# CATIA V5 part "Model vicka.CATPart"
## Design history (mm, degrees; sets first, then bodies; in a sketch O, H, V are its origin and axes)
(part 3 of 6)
    reference projected circle E1 centre (31.0473, 28.8138) radius 2.465 from edge [end face of Pad29 | face of Pad29 from Sketch61.E2]
    construction line L5 (31.0473, 24.4443) -> (31.0473, 35.3752)
    reference projected point E2 (31.0473, 28.8138) from Point1
    point P7 (36.7139, 21.5019)
    point P8 (36.1649, 23.5509)
    line L6 (36.1649, 23.5509) -> (36.7139, 21.5019)
    point P9 (36.1649, 23.5509)
    point P10 (38.1649, 27.015)
    line L7 (38.1649, 27.015) -> (36.1649, 23.5509)
    point P12 (36.7139, 21.5019)
    line L8 (36.7139, 21.5019) -> (40.2139, 27.564)
    point P13 (38.1649, 27.015)
    line L9 (40.2139, 27.564) -> (38.1649, 27.015)
    point P15 (23.9298, 27.015)
    point P16 (25.9298, 23.5509)
    line L10 (25.9298, 23.5509) -> (23.9298, 27.015)
    point P17 (25.9298, 23.5509)
    point P18 (25.3807, 21.5019)
    line L11 (25.3807, 21.5019) -> (25.9298, 23.5509)
    point P19 (21.8807, 27.564)
    point P20 (23.9298, 27.015)
    line L12 (23.9298, 27.015) -> (21.8807, 27.564)
    point P21 (25.3807, 21.5019)
    point P22 (21.8807, 27.564)
    line L13 (21.8807, 27.564) -> (25.3807, 21.5019)
    length L1 = 4
    distance L3 L1 = 1.5
    angle L2 L1 = 135
    distance L1 E1 = 4.6
    distance P3 L5 = 3.5
    distance L5 E2 = 0
    length L3 = 7
    distance P7 L5 = 5.6666
    angle L6 L1 = 255
    length L7 = 4
    distance L7 E1 = 9.5284
    angle L3 L7 = 60 (reference)
    angle L2 L7 = 15
    length L8 = 7
    distance P12 L5 = 5.6666
    angle L8 L1 = 300 (reference)
    angle L8 L7 = 180 (reference)
    length L9 = 2.1213
    length L6 = 2.1213
    distance L7 L8 = 1.5
    angle L9 L8 = 45
    length L10 = 4
    distance L10 E1 = 9.5284
    angle L3 L10 = 300 (reference)
    angle L8 L10 = 60 (reference)
    angle L6 L10 = 15
    distance P19 L5 = 9.1666
    angle L12 L1 = 15
    length L13 = 7
    distance P22 L5 = 9.1666
    angle L13 L1 = 60 (reference)
    angle L13 L10 = 180 (reference)
    angle L13 L7 = 300 (reference)
    distance L13 L10 = 1.5
    length L12 = 2.1213
    length L11 = 2.1213
    distance P18 P21 = 0
    distance P8 P9 = 0
    distance P13 P10 = 0
    horizontal: L1 H, L3 H
    vertical: L5 V
    coincidence: P20 P15, P16 P17
  Pocket16: profile Sketch62, direction (-0.9237, 0.2709, 0.2709), length 2.2
  Sketch63 on end face of Pad29, origin (-16.699, 4.8982, 4.8982), H (0.2815, 0.9596, 0), V (0.26, -0.0763, 0.9626)
    circle A1 centre (31.0473, 28.8138) radius 1.75
    reference projected circle E1 centre (31.0473, 28.8138) radius 2.465 from edge [end face of Pad29 | face of Pad29 from Sketch61.E2]
    projected circle E2 centre (31.0473, 28.8138) radius 2.465 from edge [end face of Pad29 | face of Pad29]
    radius A1 = 1.75
    concentricity: E1 A1
  Pad30: profile Sketch63, direction (-0.9237, 0.2709, 0.2709), length 2
  Sketch64 on end face of Pad30, origin (-18.5463, 5.4401, 5.4401), H (-0.2815, -0.9596, 0), V (0.26, -0.0763, 0.9626)
    point P1 (-25.9298, 23.5509)
    point P2 (-23.9298, 27.015)
    point P3 (-38.1649, 27.015)
    point P4 (-36.1649, 23.5509)
    point P5 (-29.0473, 35.8788)
    point P6 (-33.0473, 35.8788)
    line L1 (-32.4993, 26.8219) -> (-31.7921, 27.2302)
    point P8 (-31.7921, 27.2302)
    line L2 (-33.4986, 28.5543) -> (-32.791, 28.9629)
    point P9 (-33.4986, 28.5543)
    arc A1 centre (-31.0473, 28.8138) radius 2.465 from (-33.4986, 28.5543) to (-32.4993, 26.8219) ccw
    point P12 (-33.4986, 28.5543)
    arc A2 centre (-31.0473, 28.8138) radius 1.75 from (-32.791, 28.9629) to (-31.7921, 27.2302) ccw
    point P14 (-31.7921, 27.2302)
    point P15 (-29.3026, 28.9623)
    point P16 (-30.303, 27.2305)
    arc A3 centre (-31.0463, 28.8148) radius 1.75 from (-30.303, 27.2305) to (-29.3026, 28.9623) ccw
    point P18 (-32.0473, 30.2506)
    point P19 (-30.0473, 30.2493)
    arc A4 centre (-31.0483, 28.8138) radius 1.75 from (-30.0473, 30.2493) to (-32.0473, 30.2506) ccw
    point P21 (-30.0473, 30.2493)
    point P22 (-30.0473, 31.0665)
    line L3 (-30.0473, 31.0665) -> (-30.0473, 30.2493)
    point P23 (-32.0473, 30.2506)
    point P24 (-32.0473, 31.0705)
    line L4 (-32.0473, 31.0705) -> (-32.0473, 30.2506)
    point P25 (-32.0473, 31.0705)
    point P26 (-30.0473, 31.0665)
    arc A5 centre (-31.0519, 28.8154) radius 2.465 from (-30.0473, 31.0665) to (-32.0473, 31.0705) ccw
    point P28 (-29.3026, 28.9623)
    point P29 (-28.5953, 28.5539)
    line L5 (-28.5953, 28.5539) -> (-29.3026, 28.9623)
    point P30 (-28.5953, 28.5539)
    point P31 (-29.5954, 26.8219)
    arc A6 centre (-31.0465, 28.8145) radius 2.465 from (-29.5954, 26.8219) to (-28.5953, 28.5539) ccw
    point P33 (-30.303, 27.2305)
    point P34 (-29.5954, 26.8219)
    line L6 (-29.5954, 26.8219) -> (-30.303, 27.2305)
    construction line L7 (-25.9298, 23.5509) -> (-23.9298, 27.015)
    construction line L8 (-38.1649, 27.015) -> (-36.1649, 23.5509)
    construction line L9 (-29.0473, 35.8788) -> (-33.0473, 35.8788)
    distance P14 P8 = 0
    distance P12 P9 = 0
    angle L1 L8 = 90
    distance L1 P4 = 1
    distance L2 P3 = 1
    angle L4 L8 = 330 (reference)
    radius A4 = 1.75
    radius A5 = 2.465
    length L3 = 0.8171
    distance A4 L9 = 5.315
    distance A5 L9 = 4.5984
    distance L3 P5 = 1
    distance P6 L4 = 1
    angle L3 L9 = 90
    angle L4 L9 = 90
    distance P22 L9 = 4.8124
    distance P26 P22 = 0
    distance P25 P24 = 0
    distance P18 L4 = 0
    distance P19 P21 = 0
    radius A3 = 1.75
    length L5 = 0.8167
    angle L5 L7 = 90
    distance P29 L7 = 4.8099
    distance L5 P2 = 1
    radius A6 = 2.465
    distance P30 P29 = 0
    distance L6 P1 = 1
    length L6 = 0.8171
    angle L6 L7 = 90
    distance P31 P34 = 0
    distance P31 L7 = 4.81
    distance P15 P28 = 0
    distance P16 P33 = 0
    distance P23 P18 = 0
    parallelism: L2 L1
  Pad31: profile Sketch64, direction (-0.9237, 0.2709, 0.2709), length 3
  Sketch65 on end face of Pad10, origin (-3.8, 0, 0), H (0, -1, 0), V (0, 0, 1)
    line L1 (-30.2, -71.45) -> (-30.2, -54.1046)
    reference projected line E1 (-20.2, -66.45) -> (-20.2, -54.5179) from edge [face of Pad10 from Sketch17.L7 | end face of Pad10]
    projected line E2 (-32.7, -55.45) -> (-32.7, -66.45) from edge [face of Pad10 from Sketch17.L1 | end face of Pad10]
    point P3 (-32.7, -55.45)
    point P4 (-32.7, -66.45)
    projected arc E3 centre (-26.45, -66.45) radius 6.25 from (-32.7, -66.45) to (-20.2, -66.45) ccw from edge [face of Pad10 from Sketch17.A1 | end face of Pad10]
    projected arc E4 centre (-26.45, -66.45) radius 6.25 from (-32.7, -66.45) to (-30.2, -71.45) ccw from edge [face of Pad10 from Sketch17.A1 | end face of Pad10]
    point P5 (-32.7, -66.45)
    projected arc E5 centre (-32.306, -33.4535) radius 22 from (-49.1519, -47.6033) to (-32.7, -55.45) ccw from edge [face of Pad10 from Sketch17.A2 | end face of Pad10]
    projected arc E6 centre (-32.306, -33.4535) radius 22 from (-42.7, -52.8433) to (-32.7, -55.45) ccw from edge [face of Pad10 from Sketch17.A2 | end face of Pad10]
    point P8 (-32.7, -55.45)
    projected arc E7 centre (-32.4623, -37.7469) radius 17 from (-44.3509, -49.8985) to (-31.2, -54.7) ccw from edge [end face of Pad10 | face of Pocket8 from Sketch18.A19]
    projected arc E8 centre (-32.4623, -37.7469) radius 17 from (-42.1, -51.751) to (-31.2, -54.7) ccw from edge [end face of Pad10 | face of Pocket8 from Sketch18.A19]
    point P10 (-31.2, -54.7)
    projected line E9 (-31.2, -54.7) -> (-15.7, -45.4718) from edge [end face of Pad10 | face of Pocket8 from Sketch18.L1]
    projected line E10 (-31.2, -54.7) -> (-30.2, -54.1046) from edge [end face of Pad10 | face of Pocket8 from Sketch18.L1]
    point P11 (-31.2, -54.7)
    line L2 (-42.1, -51.751) -> (-42.7, -52.8433)
    point P13 (-42.1, -51.751)
    point P14 (-42.7, -52.8433)
    distance L1 E1 = 10
    distance P13 L1 = 11.9
    distance P14 L1 = 12.5
    vertical: L1 V
    coincidence: P13 E7, P14 E5, P3 P8, P4 P5, P10 P11
  Pocket17: profile Sketch65, direction (1, 0, 0), length 2
  Sketch66 on face of Pocket17, origin (-1.8, 0, 0), H (0, -1, 0), V (0, 0, 1)
    projected arc E1 centre (-32.306, -33.4535) radius 22 from (-42.7, -52.8433) to (-32.7, -55.45) ccw from edge [face of Pad10 from Sketch17.A2 | face of Pocket17]
    projected arc E2 centre (-32.306, -33.4535) radius 22 from (-42.2566, -53.0746) to (-32.9, -55.4455) ccw from edge [face of Pad10 from Sketch17.A2 | face of Pocket17]
    line L1 (-32.9, -55.4455) -> (-32.9, -55.0455)
    point P3 (-32.9, -55.4455)
    point P4 (-32.9, -55.0455)
    reference projected line E3 (-32.7, -55.45) -> (-32.7, -66.45) from edge [face of Pad10 from Sketch17.L1 | face of Pocket17]
    line L2 (-42.2566, -53.0746) -> (-42.064, -52.724)
    point P5 (-42.2566, -53.0746)
    reference projected line E4 (-42.1, -51.751) -> (-42.7, -52.8433) from edge [end face of Pad10 | face of Pocket17 from Sketch65.L2]
    offset arc E5 centre (-32.306, -33.4535) radius 21.6001 from (-42.5111, -52.4909) to (-32.6928, -55.0502) ccw from edge [face of Pad10 from Sketch17.A2 | face of Pocket17]
    offset arc E6 centre (-32.306, -33.4535) radius 21.6001 from (-42.064, -52.7239) to (-32.9, -55.0455) ccw from edge [face of Pad10 from Sketch17.A2 | face of Pocket17]
    point P9 (-32.9, -55.0455)
    point P10 (-42.064, -52.7239)
    distance E3 L1 = 0.2
    length L2 = 0.4
    distance L2 E4 = 0.5
    coincidence: P3 E1, P5 E1, E5 P9, P9 P4, L2 P10
    vertical: L1 V
  Pocket18: profile Sketch66, direction (1, 0, 0), length 1
  Sketch67 on end face of Pad10, origin (-3.8, 0, 0), H (0, -1, 0), V (0, 0, 1)
    line L1 (-29.2, -61.05) -> (-27.2, -61.05)
    line L2 (-27.2, -61.05) -> (-27.2, -54.05)
    line L3 (-27.2, -54.05) -> (-29.2, -54.05)
    line L4 (-29.2, -54.05) -> (-29.2, -61.05)
    line L5 (-26.2, -60.95) -> (-24.2, -60.95)
    line L6 (-24.2, -60.95) -> (-24.2, -52.95)
    line L7 (-24.2, -52.95) -> (-26.2, -52.95)
    line L8 (-26.2, -52.95) -> (-26.2, -60.95)
    line L9 (-23.2, -62.05) -> (-21.2, -62.05)
    line L10 (-21.2, -62.05) -> (-21.2, -50.55)
    line L11 (-21.2, -50.55) -> (-23.2, -50.55)
    line L12 (-23.2, -50.55) -> (-23.2, -62.05)
    reference projected circle E1 centre (-26.45, -66.45) radius 3 from edge [face of Hole1 | face of Pocket17]
    reference projected line E2 (-20.2, -66.45) -> (-20.2, -54.5179) from edge [face of Pad10 from Sketch17.L7 | end face of Pad10]
    reference projected circle E3 centre (-26.45, -66.45) radius 5 from edge [end face of Pad10 | face of Hole1]
    distance L9 E1 = 1.4
    length L11 = 2
    length L10 = 11.5
    distance L10 E2 = 1
    distance L5 E3 = 0.5
    length L5 = 2
    distance L6 L12 = 1
    length L8 = 8
    length L1 = 2
    distance L1 E3 = 0.4
    length L4 = 7
    distance L2 L8 = 1
    horizontal: L1 H, L3 H, L5 H, L7 H, L9 H, L11 H
    vertical: L2 V, L4 V, L6 V, L8 V, L10 V, L12 V
  Pocket19: profile Sketch67, direction (1, 0, 0), length 1
  Fillet21: radius 0.5, on edge [face of Pocket19 from Sketch67.L11 | face of Pocket19 from Sketch67.L10]; edge [face of Pocket19 from Sketch67.L12 | face of Pocket19 from Sketch67.L11]; edge [face of Pocket19 from Sketch67.L9 | face of Pocket19 from Sketch67.L12]; edge [face of Pocket19 from Sketch67.L10 | face of Pocket19 from Sketch67.L9]; edge [face of Pocket19 from Sketch67.L8 | face of Pocket19 from Sketch67.L7]; edge [face of Pocket19 from Sketch67.L7 | face of Pocket19 from Sketch67.L6]; edge [face of Pocket19 from Sketch67.L6 | face of Pocket19 from Sketch67.L5]; edge [face of Pocket19 from Sketch67.L5 | face of Pocket19 from Sketch67.L8]; edge [face of Pocket19 from Sketch67.L4 | face of Pocket19 from Sketch67.L3]; edge [face of Pocket19 from Sketch67.L3 | face of Pocket19 from Sketch67.L2]; edge [face of Pocket19 from Sketch67.L2 | face of Pocket19 from Sketch67.L1]; edge [face of Pocket19 from Sketch67.L1 | face of Pocket19 from Sketch67.L4]
  Sketch68 on end face of Pad10, origin (-3.8, 0, 0), H (0, -1, 0), V (0, 0, 1)
    projected line E1 (-58.5154, -33.035) -> (-44.3509, -49.8985) from edge [end face of Pad10 | face of Pocket8 from Sketch18.L3]
    projected line E2 (-58.3706, -33.2074) -> (-50.6526, -42.3961) from edge [end face of Pad10 | face of Pocket8 from Sketch18.L3]
    projected line E3 (-60.2, -34.45) -> (-49.1519, -47.6033) from edge [face of Pad10 from Sketch17.L2 | end face of Pad10]
    projected line E4 (-60.0552, -34.6224) -> (-52.3371, -43.8111) from edge [face of Pad10 from Sketch17.L2 | end face of Pad10]
    line L1 (-52.3371, -43.8111) -> (-50.6526, -42.3961)
    point P5 (-52.3371, -43.8111)
    point P6 (-50.6526, -42.3961)
    reference projected line E5 (-42.1, -51.751) -> (-42.7, -52.8433) from edge [end face of Pad10 | face of Pocket17 from Sketch65.L2]
    line L2 (-58.37, -33.207) -> (-60.0547, -34.622)
    point P8 (-60.0547, -34.622)
    point P9 (-58.3706, -33.2074)
    point P10 (-60.0552, -34.6224)
    distance P6 E5 = 12
    angle L2 L1 = 0
    distance P8 L1 = 12
    coincidence: P5 E3, P6 E1, L2 P9, L2 P10
    perpendicularity: L1 E1
  Pocket20: profile Sketch68, direction (1, 0, 0), length 1.4
  Sketch69 on face of Pad10 from Sketch17.L2, origin (0, 52.2635, -43.8988), H (-1, 0, 0), V (0, 0.6432, 0.7657)
    projected line E1 (2.4, 12.1145) -> (2.4, 0.1145) from edge [face of Pad10 from Sketch17.L2 | end face of Pocket20]
    point P1 (2.4, 12.1145)
    line L1 (2.4, 0.1145) -> (0, 1.1145)
    point P3 (0, 1.1145)
    line L2 (0, 1.1145) -> (0, 11.1145)
    point P4 (0, 11.1145)
    line L3 (0, 11.1145) -> (2.4, 12.1145)
    length L2 = 10
    distance P1 P4 V = 1
    coincidence: P3 V
    vertical: L2 V
  Pocket21: profile Sketch69, direction (0, -0.7657, 0.6432), length 1.4
  Sketch70 on end face of Pad10, origin (-3.8, 0, 0), H (0, -1, 0), V (0, 0, 1)
    projected line E1 (-66.0256, 4.0372) -> (-73.6417, -2.372) from edge [face of Pad10 from Sketch17.L5 | end face of Pad10]
    line L1 (-73.6417, -2.372) -> (-66.0256, -2.372)
    line L2 (-66.0256, -2.372) -> (-66.0256, 4.0372)
    horizontal: L1 H
    vertical: L2 V
  Pocket22: profile Sketch70, direction (1, 0, 0), length 2.2
  Chamfer25: length 5, angle 30, on edge [face of Pocket22 from Sketch70.L2 | face of Pocket22 from Sketch70.L1]
  Fillet22: radius 0.5, on edge [face of Pocket22 from Sketch70.L1 | face of Chamfer25]; edge [face of Chamfer25 | face of Pocket22 from Sketch70.L2]
  Sketch71 on end face of Pad10, origin (-3.8, 0, 0), H (0, -1, 0), V (0, 0, 1)
    offset arc E1 centre (-54.1388, -15.5257) radius 13 from (-65.6735, -9.5298) to (-67.0255, -17.2379) ccw from edge [end face of Pad10 | face of Pocket8 from Sketch18.A20]
    offset arc E2 centre (-54.1388, -15.5257) radius 13 from (-66.3475, -11.0596) to (-67.0255, -17.2379) ccw from edge [end face of Pad10 | face of Pocket8 from Sketch18.A20]
    offset arc E3 centre (-70.2785, -7.2128) radius 5.5 from (-71.6554, -1.888) to (-68.9633, -1.8724) ccw from edge [end face of Pad10 | face of Hole2]
    offset arc E4 centre (-70.2785, -7.2128) radius 5.5 from (-70.2854, -12.7128) to (-66.3475, -11.0596) ccw from edge [end face of Pad10 | face of Hole2]
    point P5 (-68.2239, -15.5746)
    point P6 (-71.5147, -11.6608)
    reference projected arc E5 centre (-74.0342, -17.1062) radius 5 from (-69.1412, -16.0775) to (-72.0998, -12.4956) ccw from edge [face of Pad10 from Sketch17.A3 | end face of Pad10]
    arc A1 centre (-80.614, -23.5903) radius 15 from (-67.0255, -17.2379) to (-70.2854, -12.7128) ccw
    point P8 (-70.2854, -12.7128)
    point P9 (-66.3475, -11.0596)
    reference projected arc E6 centre (-28.0396, -7.4369) radius 42 from (-69.1412, -16.0776) to (-60.2, -34.45) ccw from edge [face of Pad10 from Sketch17.A21 | end face of Pad10]
    offset arc E7 centre (-54.1388, -15.5257) radius 12.4 from (-65.1411, -9.8065) to (-66.4307, -17.1589) ccw from edge [end face of Pad10 | face of Pocket8 from Sketch18.A20]
    offset arc E8 centre (-54.1388, -15.5257) radius 12.4 from (-65.1411, -9.8065) to (-65.4926, -10.5407) ccw from edge [end face of Pad10 | face of Pocket8 from Sketch18.A20]
    point P10 (-65.1411, -9.8065)
    offset arc E9 centre (-71.4408, -6.5318) radius 7.1 from (-65.1411, -9.8065) to (-64.4767, -5.1493) ccw from edge [end face of Pad10 | face of Pocket8 from Sketch18.A21]
    offset arc E10 centre (-71.4408, -6.5318) radius 7.1 from (-65.1411, -9.8065) to (-64.4362, -5.3721) ccw from edge [end face of Pad10 | face of Pocket8 from Sketch18.A21]
    point P12 (-65.1411, -9.8065)
    offset arc E11 centre (-70.2785, -7.2128) radius 5.4 from (-71.6304, -1.9848) to (-68.9872, -1.9695) ccw from edge [end face of Pad10 | face of Hole2]
    offset arc E12 centre (-70.2785, -7.2128) radius 5.4 from (-65.8532, -10.3075) to (-65.1398, -5.5533) ccw from edge [end face of Pad10 | face of Hole2]
    line L1 (-64.4362, -5.3721) -> (-65.1398, -5.5533)
    point P16 (-64.4362, -5.3721)
    point P17 (-65.1398, -5.5533)
    line L2 (-65.4926, -10.5407) -> (-65.8532, -10.3075)
    point P18 (-65.4926, -10.5407)
    point P19 (-65.8532, -10.3075)
    offset arc E13 centre (-70.2785, -7.2128) radius 5.4 from (-71.6304, -1.9848) to (-68.9872, -1.9695) ccw from edge [end face of Pad10 | face of Hole2]
    offset arc E14 centre (-70.2785, -7.2128) radius 5.4 from (-65.3568, -4.9907) to (-68.086, -2.2779) ccw from edge [end face of Pad10 | face of Hole2]
    offset arc E15 centre (-44.4672, -1.177) radius 20.4 from (-64.8053, 0.4106) to (-64.4767, -5.1493) ccw from edge [end face of Pad10 | face of Pocket8 from Sketch18.A17]
    offset arc E16 centre (-44.4672, -1.177) radius 20.4 from (-64.8053, 0.4106) to (-64.5517, -4.751) ccw from edge [end face of Pad10 | face of Pocket8 from Sketch18.A17]
    offset arc E17 centre (26.1946, -18.2866) radius 92.9009 from (-37.9283, 48.9357) to (-64.7953, 0.4596) ccw from edge [end face of Pad10 | face of Pocket8 from Sketch18.A16]
    offset arc E18 centre (26.1946, -18.2866) radius 92.9009 from (-64.516, 1.7672) to (-64.7953, 0.4596) ccw from edge [end face of Pad10 | face of Pocket8 from Sketch18.A16]
    line L3 (-64.8053, 0.4106) -> (-64.7953, 0.4596)
    line L4 (-68.086, -2.2779) -> (-64.516, 1.7672)
    point P26 (-68.086, -2.2779)
    point P27 (-64.516, 1.7672)
    line L5 (-64.5517, -4.751) -> (-65.3568, -4.9907)
    point P28 (-64.5517, -4.751)
    point P29 (-65.3568, -4.9907)
    reference projected line E19 (-66.0256, 2.628) -> (-68.9123, -2.372) from edge [face of Chamfer25 | end face of Pad10]
    reference projected point E20 (-69.0828, -2.3579) from vertex [face of Fillet22 | face of Hole2 | end face of Pad10]
    distance P6 E5 = 1
    radius A1 = 15
    distance A1 E6 = 2
    distance P18 P9 = 1
    distance P19 P9 = 0.9
    distance P16 P9 = 6
    length L4 = 5.3952
    length L5 = 0.8401
    distance P28 E19 = 4.9659
    distance P26 E20 = 1
    coincidence: P8 E3, E1 P9, P16 E9, P17 E11, P18 E7, P19 E11, P26 E13, P27 E17, P28 E15, P29 E13, P10 P12
    tangency: E9 E7, L1 E7
  Pocket23: profile Sketch71, direction (1, 0, 0), length 1.6
  Sketch72 on end face of Pad10, origin (-3.8, 0, 0), H (0, -1, 0), V (0, 0, 1)
    offset circle E1 centre (-38.2049, 58.0324) radius 5.8 from edge [end face of Pad10 | face of Hole3]
    offset arc E2 centre (-38.2049, 58.0324) radius 5.8 from (-38.198, 52.2324) to (-33.0053, 55.4624) ccw from edge [end face of Pad10 | face of Hole3]
    offset arc E3 centre (-38.2049, 58.0324) radius 5.8 from (-42.5504, 54.191) to (-38.8967, 52.2738) ccw from edge [end face of Pad10 | face of Hole3]
    offset arc E4 centre (-38.2049, 58.0324) radius 5.8 from (-32.7092, 56.1785) to (-33.179, 60.9272) ccw from edge [end face of Pad10 | face of Hole3]
    offset arc E5 centre (-63.7184, 53.0264) radius 21.2 from (-46.8103, 40.2375) to (-42.9151, 57.1082) ccw from edge [face of Pad10 from Sketch17.A6 | end face of Pad10]
    offset arc E6 centre (-63.7184, 53.0264) radius 21.2 from (-44.451, 44.183) to (-42.5504, 54.191) ccw from edge [face of Pad10 from Sketch17.A6 | end face of Pad10]
    offset arc E7 centre (26.1946, -18.2866) radius 94.304 from (-38.8967, 49.951) to (-66.1695, 0.7427) ccw from edge [end face of Pad10 | face of Pocket8 from Sketch18.A16]
    offset arc E8 centre (26.1946, -18.2866) radius 94.304 from (-38.8967, 49.951) to (-44.451, 44.183) ccw from edge [end face of Pad10 | face of Pocket8 from Sketch18.A16]
    offset arc E9 centre (-40.4356, 56.1495) radius 6.6 from (-38.1411, 49.9612) to (-34.6881, 52.905) ccw from edge [end face of Pad10 | face of Pocket8 from Sketch18.A15]
    offset arc E10 centre (-40.4356, 56.1495) radius 6.6 from (-38.1411, 49.9612) to (-36.2293, 51.0635) ccw from edge [end face of Pad10 | face of Pocket8 from Sketch18.A15]
    offset arc E11 centre (-7.435, 25.3654) radius 38.2 from (-14.5313, 62.9006) to (-34.0258, 52.7911) ccw from edge [end face of Pad10 | face of Pocket8 from Sketch18.A14]
    offset arc E12 centre (-7.435, 25.3654) radius 38.2 from (-23.2671, 60.1302) to (-31.5993, 54.9514) ccw from edge [end face of Pad10 | face of Pocket8 from Sketch18.A14]
    offset arc E13 centre (-7.435, 25.3654) radius 38.2 from (-32.1378, 54.5033) to (-34.0258, 52.7911) ccw from edge [end face of Pad10 | face of Pocket8 from Sketch18.A14]
    line L1 (-34.0258, 52.7911) -> (-36.2293, 51.0635)
    point P9 (-36.2293, 51.0635)
    offset arc E14 centre (-26.5547, 81.2761) radius 21.4 from (-36.1437, 62.1447) to (-20.2729, 60.8189) ccw from edge [face of Pad10 from Sketch17.A8 | end face of Pad10]
    offset arc E15 centre (-26.5547, 81.2761) radius 21.4 from (-33.179, 60.9272) to (-23.2671, 60.1302) ccw from edge [face of Pad10 from Sketch17.A8 | end face of Pad10]
    line L2 (-38.8967, 49.951) -> (-38.8967, 52.2738)
    point P12 (-38.8967, 52.2738)
    line L3 (-38.198, 49.9404) -> (-38.198, 52.2324)
    point P13 (-38.198, 49.9404)
    point P14 (-38.198, 52.2324)
    line L4 (-38.1411, 49.9612) -> (-38.198, 49.9404)
    line L5 (-32.1378, 54.5033) -> (-33.0053, 55.4624)
    point P15 (-32.1378, 54.5033)
    point P16 (-33.0053, 55.4624)
    line L6 (-31.5993, 54.9514) -> (-32.7092, 56.1785)
    point P17 (-31.5993, 54.9514)
    point P18 (-32.7092, 56.1785)
    point P19 (-44.451, 44.183)
    point P20 (-44.451, 44.183)
    point P21 (-33.179, 60.9272)
    point P22 (-42.5504, 54.191)
    point P23 (-42.5504, 54.191)
    point P24 (-23.2671, 60.1302)
    point P25 (-33.179, 60.9272)
    length L1 = 2.8
    angle L3 L2 = 0
    distance P14 P12 = 0.7
    length L5 = 1.2933
    distance L6 L5 = 0.7
    coincidence: P9 E9, P12 E1, P13 E9, P14 E1, P15 E11, P16 E1, P17 E11, P18 E1, E7 P19, E5 P20, E14 P21, E5 P22, E1 P23, E11 P24, E1 P25, P19 P20, P21 P25, P22 P23
    vertical: L2 V
    tangency: L6 E14
  Pocket24: profile Sketch72, direction (1, 0, 0), length 1.6
  Fillet23: radius 0.5, on edge [face of Pocket23 from Sketch71.L4 | face of Pocket23 from Sketch71.E18]
  Fillet24: radius 0.5, on edge [face of Pocket23 from Sketch71.E14 | face of Pocket23 from Sketch71.L4]; edge [face of Pocket23 from Sketch71.L5 | face of Pocket23 from Sketch71.E14]; edge [face of Pocket23 from Sketch71.E16 | face of Pocket23 from Sketch71.L5]; edge [face of Pocket23 from Sketch71.E2 | face of Pocket23 from Sketch71.A1]; edge [face of Pocket23 from Sketch71.E4 | face of Pocket23 from Sketch71.E2]; edge [face of Pocket23 from Sketch71.A1 | face of Pocket23 from Sketch71.E4]
  Fillet25: radius 0.15, on edge [face of Pocket23 from Sketch71.L1 | face of Pocket23 from Sketch71.E10]; edge [face of Pocket23 from Sketch71.E12 | face of Pocket23 from Sketch71.L1]; edge [face of Pocket23 from Sketch71.L2 | face of Pocket23 from Sketch71.E12]; edge [face of Pocket23 from Sketch71.E8 | face of Pocket23 from Sketch71.L2]
  Fillet26: radius 0.15, on edge [face of Hole2 | face of Pocket22 from Sketch70.L1]
  Fillet27: radius 0.5, on edge [face of Pocket24 from Sketch72.E8 | face of Pocket24 from Sketch72.E6]; edge [face of Pocket24 from Sketch72.L2 | face of Pocket24 from Sketch72.E8]; edge [face of Pocket24 from Sketch72.E4 | face of Pocket24 from Sketch72.L2]; edge [face of Pocket24 from Sketch72.E6 | face of Pocket24 from Sketch72.E4]; edge [face of Pocket24 from Sketch72.L4 | face of Pocket24 from Sketch72.L3]; edge [face of Pocket24 from Sketch72.L3 | face of Pocket24 from Sketch72.E4]; edge [face of Pocket24 from Sketch72.E4 | face of Pocket24 from Sketch72.L5]; edge [face of Pocket24 from Sketch72.L5 | face of Pocket24 from Sketch72.E13]; edge [face of Pocket24 from Sketch72.E4 | face of Pocket24 from Sketch72.E15]; edge [face of Pocket24 from Sketch72.L6 | face of Pocket24 from Sketch72.E4]; edge [face of Pocket24 from Sketch72.E13 | face of Pocket24 from Sketch72.L6]; edge [face of Pocket24 from Sketch72.E15 | face of Pocket24 from Sketch72.E13]
  Sketch73 on end face of Pad10, origin (-3.8, 0, 0), H (0, -1, 0), V (0, 0, 1)
    offset arc E1 centre (8.752, 43.4387) radius 21.9 from (26.5109, 56.254) to (7.4681, 65.301) ccw from edge [end face of Pad10 | face of Pocket8 from Sketch18.A13]
    offset arc E2 centre (8.752, 43.4387) radius 21.9 from (26.5109, 56.254) to (17.9089, 63.3324) ccw from edge [end face of Pad10 | face of Pocket8 from Sketch18.A13]
    offset arc E3 centre (31.5751, 59.656) radius 6.1 from (26.5388, 56.2142) to (31.6843, 53.5569) ccw from edge [end face of Pad10 | face of Pocket8 from Sketch18.A12]
    offset arc E4 centre (31.5751, 59.656) radius 6.1 from (26.5388, 56.2142) to (28.1288, 54.6228) ccw from edge [end face of Pad10 | face of Pocket8 from Sketch18.A12]
    offset arc E5 centre (31.5751, 59.656) radius 6.1 from (28.7489, 54.2502) to (31.6843, 53.5569) ccw from edge [end face of Pad10 | face of Pocket8 from Sketch18.A12]
    point P4 (31.6843, 53.5569)
    line L1 (26.5388, 56.2142) -> (26.5109, 56.254)
    offset arc E6 centre (31.8974, 41.6588) radius 11.9 from (39.574, 50.7516) to (31.6843, 53.5569) ccw from edge [end face of Pad10 | face of Pocket8 from Sketch18.A11]
    offset arc E7 centre (31.8974, 41.6588) radius 11.9 from (39.574, 50.7516) to (36.2788, 52.7229) ccw from edge [end face of Pad10 | face of Pocket8 from Sketch18.A11]
    offset arc E8 centre (31.8974, 41.6588) radius 11.9 from (35.6083, 52.9654) to (31.6843, 53.5569) ccw from edge [end face of Pad10 | face of Pocket8 from Sketch18.A11]
    point P6 (31.6843, 53.5569)
    offset arc E9 centre (2.5847, 1.1235) radius 61.8964 from (60.7417, 22.3114) to (39.4787, 50.8225) ccw from edge [end face of Pad10 | face of Pocket8 from Sketch18.A10]
    offset arc E10 centre (2.5847, 1.1235) radius 61.8964 from (41.27, 49.4413) to (39.574, 50.7516) ccw from edge [end face of Pad10 | face of Pocket8 from Sketch18.A10]
    offset arc E11 centre (56.2086, 56.68) radius 16.6 from (39.6527, 57.889) to (44.5372, 44.8758) ccw from edge [face of Pad10 from Sketch17.A24 | end face of Pad10]
    offset arc E12 centre (56.2086, 56.68) radius 16.6 from (39.6314, 55.8102) to (41.27, 49.4413) ccw from edge [face of Pad10 from Sketch17.A24 | end face of Pad10]
    offset circle E13 centre (35.6864, 59.6426) radius 5.5 from edge [end face of Pad10 | face of Hole4]
    offset arc E14 centre (35.6864, 59.6426) radius 5.5 from (31.1959, 62.8183) to (30.7595, 57.1981) ccw from edge [end face of Pad10 | face of Hole4]
    offset arc E15 centre (35.6864, 59.6426) radius 5.5 from (31.1222, 56.5737) to (35.7931, 54.1436) ccw from edge [end face of Pad10 | face of Hole4]
    offset arc E16 centre (35.6864, 59.6426) radius 5.5 from (36.5112, 54.2048) to (39.6314, 55.8102) ccw from edge [end face of Pad10 | face of Hole4]
    offset arc E17 centre (25.4433, 83.6382) radius 21.6 from (19.4377, 62.8899) to (33.85, 63.7413) ccw from edge [face of Pad10 from Sketch17.A23 | end face of Pad10]
    offset arc E18 centre (25.4433, 83.6382) radius 21.6 from (19.4377, 62.8899) to (31.1959, 62.8183) ccw from edge [face of Pad10 from Sketch17.A23 | end face of Pad10]
    line L2 (19.4377, 62.8899) -> (17.9089, 63.3324)
    point P13 (17.9089, 63.3324)
    line L3 (28.1288, 54.6228) -> (30.7595, 57.1981)
    point P14 (28.1288, 54.6228)
    point P15 (30.7595, 57.1981)
    line L4 (28.7489, 54.2502) -> (31.1222, 56.5737)
    point P16 (28.7489, 54.2502)
    point P17 (31.1222, 56.5737)
    line L5 (36.2788, 52.7229) -> (36.5112, 54.2048)
    point P18 (36.2788, 52.7229)
    point P19 (36.5112, 54.2048)
    line L6 (35.6083, 52.9654) -> (35.7931, 54.1436)
    point P20 (35.6083, 52.9654)
    reference projected point E19 (38.3483, 49.2998) from vertex [face of Pocket8 from Sketch18.A11 | end face of Pad10 | face of Pocket8 from Sketch18.A10]
    point P22 (41.27, 49.4413)
    point P23 (39.6314, 55.8102)
    point P24 (39.6314, 55.8102)
    point P25 (31.1959, 62.8183)
    length L3 = 3.6814
    distance L3 L4 = 0.7
    length L5 = 1.5
    distance L5 L6 = 0.7
    distance P18 E19 = 4
    tangency: E6 E3, L2 E17, L3 E6
    coincidence: P13 E1, P14 E3, P15 E13, P16 E3, P17 E13, P18 E6, P19 E13, P20 E6, E9 P22, E13 P23, E11 P24, E17 P25, P4 P6, P23 P24
  Pocket25: profile Sketch73, direction (1, 0, 0), length 1.6
  Fillet28: radius 0.5, on edge [face of Pocket25 from Sketch73.E2 | face of Pocket25 from Sketch73.L2]; edge [face of Pocket25 from Sketch73.E18 | face of Pocket25 from Sketch73.E16]; edge [face of Pocket25 from Sketch73.E16 | face of Pocket25 from Sketch73.L3]; edge [face of Pocket25 from Sketch73.L3 | face of Pocket25 from Sketch73.E5]; edge [face of Pocket25 from Sketch73.E5 | face of Pocket25 from Sketch73.L4]; edge [face of Pocket25 from Sketch73.L4 | face of Pocket25 from Sketch73.E16]; edge [face of Pocket25 from Sketch73.E16 | face of Pocket25 from Sketch73.L6]; edge [face of Pocket25 from Sketch73.L6 | face of Pocket25 from Sketch73.E8]; edge [face of Pocket25 from Sketch73.E16 | face of Pocket25 from Sketch73.E12]; edge [face of Pocket25 from Sketch73.E8 | face of Pocket25 from Sketch73.L5]; edge [face of Pocket25 from Sketch73.L5 | face of Pocket25 from Sketch73.E16]; edge [face of Pocket25 from Sketch73.E12 | face of Pocket25 from Sketch73.E10]
  Sketch74 on end face of Pad10, origin (-3.8, 0, 0), H (0, -1, 0), V (0, 0, 1)
    offset arc E1 centre (-34.9988, -12.569) radius 101.9 from (62.6472, 16.5664) to (60.7451, 22.3126) ccw from edge [end face of Pad10 | face of Pocket8 from Sketch18.A9]
    offset arc E2 centre (-34.9988, -12.569) radius 101.9 from (62.6472, 16.5664) to (60.9852, 21.6465) ccw from edge [end face of Pad10 | face of Pocket8 from Sketch18.A9]
    offset arc E3 centre (72.4489, 33.5138) radius 16.5 from (57.498, 26.5337) to (68.3641, 17.5274) ccw from edge [face of Pad10 from Sketch17.A25 | end face of Pad10]
    offset arc E4 centre (72.4489, 33.5138) radius 16.5 from (60.9852, 21.6465) to (65.7293, 18.444) ccw from edge [face of Pad10 from Sketch17.A25 | end face of Pad10]
    offset circle E5 centre (68.2522, 13.0002) radius 6 from edge [end face of Pad10 | face of Hole5]
    offset arc E6 centre (68.2522, 13.0002) radius 6 from (63.024, 10.0565) to (69.7185, 7.1821) ccw from edge [end face of Pad10 | face of Hole5]
    offset arc E7 centre (68.2522, 13.0002) radius 6 from (65.7293, 18.444) to (62.7907, 15.4845) ccw from edge [end face of Pad10 | face of Hole5]
    offset arc E8 centre (45.9426, 14.1611) radius 16.9 from (62.8297, 13.5008) to (62.7118, 16.259) ccw from edge [end face of Pad10 | face of Pocket8 from Sketch18.A8]
    offset arc E9 centre (45.9426, 14.1611) radius 16.9 from (62.7907, 15.4845) to (62.7118, 16.259) ccw from edge [end face of Pad10 | face of Pocket8 from Sketch18.A8]
    line L1 (62.7118, 16.259) -> (62.6472, 16.5664)
    offset arc E10 centre (80.3386, 2.516) radius 11.6 from (71.576, 10.117) to (68.7909, 1.4154) ccw from edge [face of Pad10 from Sketch17.A13 | end face of Pad10]
    offset arc E11 centre (80.3386, 2.516) radius 11.6 from (69.7185, 7.1821) to (68.7909, 1.4154) ccw from edge [face of Pad10 from Sketch17.A13 | end face of Pad10]
    point P8 (68.7909, 1.4154)
    offset arc E12 centre (80.9158, 12.7935) radius 18.1 from (62.8297, 13.5008) to (65.9716, 2.5816) ccw from edge [end face of Pad10 | face of Pocket8 from Sketch18.A7]
    offset arc E13 centre (80.9158, 12.7935) radius 18.1 from (63.024, 10.0565) to (65.9716, 2.5816) ccw from edge [end face of Pad10 | face of Pocket8 from Sketch18.A7]
    offset arc E14 centre (37.3391, -11.4343) radius 31.9 from (68.7866, -16.7883) to (66.117, 2.3295) ccw from edge [end face of Pad10 | face of Pocket8 from Sketch18.A6]
    offset arc E15 centre (37.3391, -11.4343) radius 31.9 from (68.9686, -7.2888) to (66.117, 2.3295) ccw from edge [end face of Pad10 | face of Pocket8 from Sketch18.A6]
    offset arc E16 centre (10.6543, -4.1251) radius 58.4 from (65.0707, -25.3247) to (68.7909, 1.4155) ccw from edge [face of Pad10 from Sketch17.A14 | end face of Pad10]
    offset arc E17 centre (10.6543, -4.1251) radius 58.4 from (68.9686, -7.2888) to (68.7909, 1.4155) ccw from edge [face of Pad10 from Sketch17.A14 | end face of Pad10]
    point P14 (68.7909, 1.4155)
    line L2 (66.117, 2.3295) -> (65.9716, 2.5816)
    point P15 (69.7185, 7.1821)
    point P16 (68.9686, -7.2888)
    point P17 (68.9686, -7.2888)
    point P18 (63.024, 10.0565)
    point P19 (62.7907, 15.4845)
    point P20 (63.024, 10.0565)
    point P21 (62.7907, 15.4845)
    point P22 (65.7293, 18.444)
    point P23 (69.7185, 7.1821)
    point P24 (65.7293, 18.444)
    point P25 (60.9852, 21.6465)
    tangency: E16 E10
    coincidence: E5 P15, E14 P16, E16 P17, E5 P18, E8 P19, E12 P20, E5 P21, E5 P22, E10 P23, E3 P24, E1 P25, P8 P14, P15 P23, P16 P17, P18 P20, P19 P21, P22 P24
  Pocket26: profile Sketch74, direction (1, 0, 0), length 1.6
  Fillet29: radius 0.5, on edge [face of Pocket26 from Sketch74.E17 | face of Pocket26 from Sketch74.E15]
  Fillet30: radius 1, on edge [face of Pocket26 from Sketch74.E13 | face of Pocket26 from Sketch74.E7]
  Fillet31: radius 0.5, on edge [face of Pocket26 from Sketch74.E7 | face of Pocket26 from Sketch74.E11]
  Fillet32: radius 0.5, on edge [face of Pocket26 from Sketch74.E4 | face of Pocket26 from Sketch74.E7]
  Fillet33: radius 0.3, on edge [face of Pocket26 from Sketch74.E7 | face of Pocket26 from Sketch74.E9]
  Fillet34: radius 0.5, on edge [face of Pocket26 from Sketch74.E2 | face of Pocket26 from Sketch74.E4]
  Sketch75 on end face of Pad10, origin (-3.8, 0, 0), H (0, -1, 0), V (0, 0, 1)
    offset arc E1 centre (32.0711, -43.2237) radius 13.9 from (19.7631, -49.6829) to (37.3705, -56.0738) ccw from edge [end face of Pad10 | face of Pocket8 from Sketch18.A4]
    offset arc E2 centre (32.0711, -43.2237) radius 13.9 from (21.5, -52.2493) to (23.8, -54.395) ccw from edge [end face of Pad10 | face of Pocket8 from Sketch18.A4]
    offset arc E3 centre (32.0711, -43.2237) radius 13.9 from (29.8, -56.9369) to (33.5274, -57.0472) ccw from edge [end face of Pad10 | face of Pocket8 from Sketch18.A4]
    offset arc E4 centre (32.0711, -43.2237) radius 13.9 from (24.7, -55.0083) to (28.5, -56.6571) ccw from edge [end face of Pad10 | face of Pocket8 from Sketch18.A4]
    offset circle E5 centre (26.2, -66.08) radius 5.8 from edge [end face of Pad10 | face of Hole6]
    offset arc E6 centre (26.2, -66.08) radius 5.8 from (30.73, -62.458) to (29.8, -61.5325) ccw from edge [end face of Pad10 | face of Hole6]
    offset arc E7 centre (26.2, -66.08) radius 5.8 from (23.8, -60.7999) to (21.5, -62.6815) ccw from edge [end face of Pad10 | face of Hole6]
    offset arc E8 centre (26.2, -66.08) radius 5.8 from (28.5, -60.7556) to (24.7, -60.4774) ccw from edge [end face of Pad10 | face of Hole6]
    offset line E9 (21.5, -52.2166) -> (21.5, -66.08) from edge [face of Pad10 from Sketch17.L6 | end face of Pad10]
    offset line E10 (21.5, -52.2493) -> (21.5, -62.6815) from edge [face of Pad10 from Sketch17.L6 | end face of Pad10]
    line L1 (23.8, -54.395) -> (23.8, -60.7999)
    construction line L2 (21.5, -52.2166) -> (23.8, -52.2166)
    construction line L3 (21.5, -66.08) -> (23.8, -66.08)
    line L4 (24.7, -55.0083) -> (24.7, -60.4774)
    construction line L5 (23.8, -52.2166) -> (24.7, -52.2166)
    construction line L6 (23.8, -66.08) -> (24.7, -66.08)
    line L7 (28.5, -56.6571) -> (28.5, -60.7556)
    construction line L8 (24.7, -52.2166) -> (28.5, -52.2166)
    construction line L9 (24.7, -66.08) -> (28.5, -66.08)
    line L10 (29.8, -56.9369) -> (29.8, -61.5325)
    construction line L11 (28.5, -52.2166) -> (29.8, -52.2166)
    construction line L12 (28.5, -66.08) -> (29.8, -66.08)
    offset arc E11 centre (38.7, -63.15) radius 8 from (35.7271, -55.7229) to (30.7285, -63.8244) ccw from edge [face of Pad10 | end face of Pad10]
    offset arc E12 centre (38.7, -63.15) radius 8 from (33.5274, -57.0472) to (30.73, -62.458) ccw from edge [face of Pad10 | end face of Pad10]
    point P15 (21.5, -52.2493)
    point P16 (23.8, -54.395)
    point P17 (24.7, -55.0083)
    point P18 (28.5, -56.6571)
    point P19 (29.8, -56.9369)
    point P20 (33.5274, -57.0472)
    point P21 (33.5274, -57.0472)
    point P22 (21.5, -62.6815)
    point P23 (30.73, -62.458)
    point P24 (29.8, -61.5325)
    point P25 (28.5, -60.7556)
    point P26 (24.7, -60.4774)
    point P27 (23.8, -60.7999)
    point P28 (21.5, -62.6815)
    point P29 (21.5, -52.2493)
    distance E9 L1 = 2.3
    distance L1 L4 = 0.9
    distance L4 L7 = 3.8
    distance L7 L10 = 1.3
    perpendicularity: L2 E9, L2 L1, L3 E9, L3 L1, L5 L1, L5 L4, L6 L1, L6 L4, L8 L4, L8 L7, L9 L4, L9 L7, L11 L7, L11 L10, L12 L7, L12 L10
    coincidence: E9 P15, E1 P16, E1 P17, E1 P18, E1 P19, E1 P20, E11 P21, E9 P22, E11 P23, E5 P24, E5 P25, E5 P26, E5 P27, E5 P28, E1 P29, P15 P29, P20 P21, P22 P28
  Pocket27: profile Sketch75, direction (1, 0, 0), length 1.6
  Fillet35: radius 0.5, on edge [face of Pocket27 from Sketch75.E4 | face of Pocket27 from Sketch75.E12]; edge [face of Pocket27 from Sketch75.L10 | face of Pocket27 from Sketch75.E4]; edge [face of Pocket27 from Sketch75.E12 | face of Pocket27 from Sketch75.E8]; edge [face of Pocket27 from Sketch75.E8 | face of Pocket27 from Sketch75.L10]; edge [face of Pocket27 from Sketch75.L7 | face of Pocket27 from Sketch75.E8]; edge [face of Pocket27 from Sketch75.E4 | face of Pocket27 from Sketch75.L7]; edge [face of Pocket27 from Sketch75.L4 | face of Pocket27 from Sketch75.E4]; edge [face of Pocket27 from Sketch75.E8 | face of Pocket27 from Sketch75.L4]; edge [face of Pocket27 from Sketch75.E4 | face of Pocket27 from Sketch75.L1]; edge [face of Pocket27 from Sketch75.E10 | face of Pocket27 from Sketch75.E4]; edge [face of Pocket27 from Sketch75.L1 | face of Pocket27 from Sketch75.E8]; edge [face of Pocket27 from Sketch75.E8 | face of Pocket27 from Sketch75.E10]
  Sketch76 on end face of Pad10, origin (-3.8, 0, 0), H (0, -1, 0), V (0, 0, 1)
    projected arc E1 centre (15.8905, -6.165) radius 54.3805 from (36.0987, -56.6513) to (66.5615, -25.9055) ccw from edge [face of Pad10 from Sketch17.A15 | end face of Pad10]
    projected arc E2 centre (15.8905, -6.165) radius 54.3805 from (41.8055, -53.9735) to (66.5615, -25.9055) ccw from edge [face of Pad10 from Sketch17.A15 | end face of Pad10]
    projected arc E3 centre (17.6228, -8.0776) radius 50 from (36.6462, -54.3173) to (66.9135, -16.4694) ccw from edge [end face of Pad10 | face of Pocket8 from Sketch18.A5]
    projected arc E4 centre (17.6228, -8.0776) radius 50 from (40.9389, -52.3084) to (66.9135, -16.4694) ccw from edge [end face of Pad10 | face of Pocket8 from Sketch18.A5]
    projected arc E5 centre (10.6543, -4.1251) radius 60 from (66.5615, -25.9055) to (70.3837, 1.5673) ccw from edge [face of Pad10 from Sketch17.A14 | end face of Pad10]
    projected arc E6 centre (10.6543, -4.1251) radius 60 from (66.5615, -25.9055) to (69.253, -17.0166) ccw from edge [face of Pad10 from Sketch17.A14 | end face of Pad10]
    line L1 (41.8055, -53.9735) -> (40.9389, -52.3084)
    point P7 (41.8055, -53.9735)
    point P8 (40.9389, -52.3084)
    reference projected point E7 (43.5459, -57.3175) from vertex [face of Pad4 from Sketch6.L2 | face of Pad4 | face of Fillet1]
    line L2 (66.9135, -16.4694) -> (69.253, -17.0166)
    point P9 (69.253, -17.0166)
    reference projected circle E8 centre (68.2522, 13.0002) radius 5 from edge [end face of Pad10 | face of Hole5]
    point P10 (40.9389, -52.3084)
    point P11 (41.8055, -53.9735)
    distance L1 E7 = 0
    distance P8 E7 = 5.6469
    distance L2 E8 = 24
    coincidence: P7 E1, P8 E3, P9 E5, L1 P10, L1 P11, P7 P11
  Pocket28: profile Sketch76, direction (1, 0, 0), length 0.7
  Sketch77 on end face of Pad10, origin (-3.8, 0, 0), H (0, -1, 0), V (0, 0, 1)
    circle A1 centre (-8.6256, 68.8636) radius 5.2
    reference projected circle E1 centre (-38.2049, 58.0324) radius 5 from edge [end face of Pad10 | face of Hole3]
    reference projected line E2 (-13.3045, 53.6631) -> (8.0778, 54.9189) from edge [face of Pad12 from Sketch20.E34 | face of Fillet15]
    radius A1 = 5.2
    distance A1 E1 = 21.3
    distance A1 E2 = 9.7
  Pocket29: profile Sketch77, direction (1, 0, 0), length 4.3
  Sketch78 on face of Pad9, origin (0, 0, 0), H (0, -1, 0), V (0, 0, 1)
    projected line E1 (-66.0256, 4.0372) -> (-73.6417, -2.372) from edge [face of Pad10 from Sketch17.L5 | end face of Pocket22]
    projected line E2 (-66.0256, 4.0372) -> (-71.7145, -0.7502) from edge [face of Pad10 from Sketch17.L5 | end face of Pocket22]
    point P1 (-66.0256, 4.0372)
    arc A1 centre (-69.2785, 3.7872) radius 5.15 from (-65.1849, 6.9121) to (-71.7145, -0.7502) ccw
    point P3 (-69.2785, 3.7872)
    reference projected point E3 (-70.2785, -7.2128) from Sketch44.P3
    projected arc E4 centre (39.9635, -25.3959) radius 110 from (-47.7674, 40.9614) to (-66.0256, 4.0372) ccw from edge [face of Pad10 from Sketch17.A5 | end face of Pad10]
    projected arc E5 centre (39.9635, -25.3959) radius 110 from (-65.1849, 6.9121) to (-66.0256, 4.0372) ccw from edge [face of Pad10 from Sketch17.A5 | end face of Pad10]
    point P5 (-66.0256, 4.0372)
    point P7 (-71.7145, -0.7502)
    radius A1 = 5.15
    distance P3 E3 H = 1
    distance P3 E3 V = 11
    coincidence: E1 P7, P1 P5
  Pocket30: profile Sketch78, direction (1, 0, 0), length 0.6
  Sketch79 on zx-plane, origin (0, 0, 0), H (-1, 0, 0), V (0, 0, 1)
    point P1 (-1.6, -39.5)
    line L1 (-1.6, -39.5) -> (-1.6, -35.2)
    line L2 (-1.6, -35.2) -> (2.3, -36.2)
    line L3 (2.3, -36.2) -> (2.3, -39.5)
    line L4 (2.3, -39.5) -> (-1.6, -39.5)
    reference projected line E1 (-1.6, -40.2888) -> (-1.6, -39.9658) from Sketch80.E4
    distance P1 E1 = 0
    length L1 = 4.3
    length L3 = 3.3
    length L4 = 3.9
    distance L4 H = 39.5
    vertical: L1 V, L3 V
    horizontal: L4 H
  Sketch80 on face of Pad9, origin (1.6, 0, 0), H (0, 1, 0), V (0, 0, 1)
    projected arc E1 centre (-1.1744, -116.1681) radius 76.2024 from (-5.7125, -40.101) to (-16.6339, -41.5504) ccw from edge [face of Pad11 from Sketch19.C3 | face of Pad21 from Sketch35.E5]
    point P2 (-16.6339, -41.5504)
    projected arc E2 centre (-14.3612, -52.5182) radius 11.2008 from (-16.6339, -41.5504) to (-24.279, -47.313) ccw from edge [face of Pad11 from Sketch19.C2 | face of Pad21 from Sketch35.E3]
    projected arc E3 centre (-14.3612, -52.5182) radius 11.2008 from (-16.6339, -41.5504) to (-23.8967, -46.6419) ccw from edge [face of Pad11 from Sketch19.C2 | face of Pad21 from Sketch35.E3]
    point P3 (-16.6339, -41.5504)
    projected arc E4 centre (-1.1744, -116.1703) radius 76.2045 from (5.8345, -40.2888) to (-5.7125, -40.101) ccw from edge [face of Pad11 from Sketch19.C3 | face of Pad13]
    coincidence: P2 P3
  Slot1: profile Sketch79, centre curve Sketch80
  Plane5: type Offset, RefPlane face of Slot1, Offset 3
  Sketch81 on Plane5, origin (0, 11.8693, -0.9121), H (-1, 0, 0), V (0, 0.0766, 0.9971)
    projected line E1 (-1.6, -34.9485) -> (-1.6, -39.2485) from edge [face of Slot1 | face of Pad9]
    line L1 (-1.6, -34.9485) -> (6.4, -39.2485)
    point P3 (6.4, -39.2485)
    line L2 (-1.6, -39.2485) -> (6.4, -39.2485)
    point P4 (6.4, -39.2485)
    length L2 = 8
    distance P3 P4 = 0
    horizontal: L2 H
  Sketch82 on face of Pad9, origin (1.6, 0, 0), H (0, 1, 0), V (0, 0, 1)
    projected arc E1 centre (12.1074, -51.5204) radius 14.2479 from (19.3904, -39.2745) to (13.9573, -37.3931) ccw from edge [face of Chamfer18 | end face of Pad20]
    projected line E2 (19.3898, -39.2742) -> (19.7783, -39.5055) from edge [face of Chamfer18 | end face of Pad20]
    projected arc E3 centre (-1.1744, -116.1678) radius 80.2149 from (13.9573, -37.3931) to (8.2896, -36.5132) ccw from edge [face of Chamfer18 | end face of Pad20]
    line L1 (8.2896, -36.5132) -> (7.4363, -36.4118)
    point P7 (7.4363, -36.4118)
    reference projected line E4 (6.2004, -35.528) -> (5.8709, -39.8154) from edge [face of Slot1 | face of Pad9]
    distance P7 E4 = 1.3
    tangency: L1 E3
  Slot2: profile Sketch81, centre curve Sketch82
  Sketch83 on face of Pad9, origin (1.6, 0, 0), H (0, 1, 0), V (0, 0, 1)
    projected arc E1 centre (-1.1744, -116.1688) radius 80.9773 from (6.2004, -35.528) to (-6.0703, -35.3396) ccw from edge [face of Pad9 | face of Slot1]
    projected arc E2 centre (-1.1744, -116.1688) radius 80.9773 from (-2.4854, -35.2021) to (-3.9229, -35.2381) ccw from edge [face of Pad9 | face of Slot1]
    projected arc E3 centre (-1.1688, -116.2099) radius 81.0186 from (-6.0703, -35.3396) to (-17.6747, -36.8904) ccw from edge [face of Pad9 | face of Slot1]
    projected arc E4 centre (-1.1688, -116.2099) radius 81.0186 from (-12.5229, -35.9908) to (-13.8229, -36.1855) ccw from edge [face of Pad9 | face of Slot1]
    projected arc E5 centre (-1.1681, -116.2152) radius 76.7245 from (-5.7481, -39.6275) to (-16.7374, -41.087) ccw from edge [face of Slot1 | face of Pad9]
    projected arc E6 centre (-1.1681, -116.2152) radius 76.7245 from (-12.5229, -40.3356) to (-13.8229, -40.5415) ccw from edge [face of Slot1 | face of Pad9]
    projected arc E7 centre (-1.1744, -116.1688) radius 76.6778 from (5.8709, -39.8154) to (-5.7481, -39.6275) ccw from edge [face of Slot1 | face of Pad9]
    projected arc E8 centre (-1.1744, -116.1688) radius 76.6778 from (-2.6234, -39.5047) to (-3.9229, -39.5403) ccw from edge [face of Slot1 | face of Pad9]
    point P7 (5.8709, -39.8154)
    projected arc E9 centre (12.1074, -51.5204) radius 10.8157 from (17.789, -42.3172) to (13.3982, -40.782) ccw from edge [face of Slot2 | face of Pad9]
    projected arc E10 centre (12.1074, -51.5204) radius 10.8157 from (17.5, -42.1449) to (16.2, -41.5089) ccw from edge [face of Slot2 | face of Pad9]
    projected arc E11 centre (12.1074, -51.5204) radius 15.1085 from (19.7917, -38.512) to (14.0939, -36.5431) ccw from edge [face of Pad9 | face of Slot2]
    projected arc E12 centre (12.1074, -51.5204) radius 15.1085 from (17.5, -37.4071) to (16.2, -36.9768) ccw from edge [face of Pad9 | face of Slot2]
    line L1 (-13.8229, -40.5415) -> (-13.8229, -36.1855)
    point P13 (-13.8229, -40.5415)
    point P14 (-13.8229, -36.1855)
    line L2 (-12.5229, -40.3356) -> (-12.5229, -35.9908)
    point P15 (-12.5229, -40.3356)
    point P16 (-12.5229, -35.9908)
    line L3 (-3.9229, -39.5403) -> (-3.9229, -35.2381)
    point P17 (-3.9229, -39.5403)
    point P18 (-3.9229, -35.2381)
    line L4 (-2.6234, -39.5047) -> (-2.4854, -35.2021)
    point P19 (-2.6234, -39.5047)
    point P20 (-2.4854, -35.2021)
    line L5 (16.2, -41.5089) -> (16.2, -36.9768)
    point P21 (16.2, -41.5089)
    point P22 (16.2, -36.9768)
    line L6 (17.5, -42.1449) -> (17.5, -37.4071)
    point P23 (17.5, -42.1449)
    point P24 (17.5, -37.4071)
    reference projected line E13 (19.7, -73.2) -> (19.7, -54.5084) from edge [face of Pad9 | face of Pad3]
    distance L5 E13 = 3.5
    distance L6 L5 = 1.3
    distance P19 P7 = 8.5
    distance P17 P19 = 1.3
    distance L2 L3 = 8.6
    distance L2 L1 = 1.3
    coincidence: P13 E5, P14 E3, P15 E5, P16 E3, P17 E7, P18 E1, P19 E7, P20 E1, P21 E9, P22 E11, P23 E9, P24 E11
    vertical: L1 V, L2 V, L3 V, L5 V, L6 V
    tangency: L4 E11
  Pad32: profile Sketch83, direction (-1, 0, 0), up to the existing solid (limit type 2)
  Chamfer26: length 3.9, angle 18, on edge [face of Pad32 | face of Slot1]
  Chamfer27: length 7.989, angle 10, on edge [face of Slot2 | face of Pad32]
  Sketch84 on xy-plane, origin (0, 0, 0), H (1, 0, 0), V (0, 1, 0)
    point P1 (1.6, -56)
    line L1 (1.6, -56) -> (1.6, -60.3)
    line L2 (1.6, -60.3) -> (-2.4, -60.3)
    line L3 (-2.4, -60.3) -> (-2.4, -57)
    line L4 (-2.4, -57) -> (1.6, -56)
    reference projected line E1 (1.6, 71.425) -> (1.6, -71.425) from edge [face of Pad1 from Sketch1.A1 | face of Pad32]
    length L1 = 4.3
    distance P1 H = 56
    length L3 = 3.3
    length L2 = 4
    distance L1 E1 = 0
    vertical: L1 V, L3 V
    horizontal: L2 H
  Sketch85 on face of Pad32, origin (1.6, 0, 0), H (0, 1, 0), V (0, 0, 1)
    projected arc E1 centre (-17.6227, -8.0775) radius 42.0001 from (-59.027, -15.1267) to (-57.9293, -19.8837) ccw from edge [face of Fillet16 | face of Pad13]
    projected arc E2 centre (-37.3365, -11.4347) radius 22.0025 from (-57.403, -2.4101) to (-59.027, -15.1267) ccw from edge [face of Fillet16 | face of Pad13]
    projected arc E3 centre (-80.9165, 12.7936) radius 28.0006 from (-57.403, -2.4101) to (-52.9372, 13.8876) ccw from edge [face of Fillet16 | face of Pad13]
    projected arc E4 centre (35.0097, -12.5726) radius 92.0115 from (-51.4432, 18.9237) to (-52.9353, 14.479) ccw from edge [face of Fillet16 | face of Pad13]
    projected arc E5 centre (-45.939, 14.1611) radius 7.0035 from (-52.9353, 14.479) to (-52.9372, 13.8876) ccw from edge [face of Fillet16 | face of Pad13]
